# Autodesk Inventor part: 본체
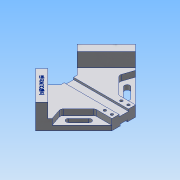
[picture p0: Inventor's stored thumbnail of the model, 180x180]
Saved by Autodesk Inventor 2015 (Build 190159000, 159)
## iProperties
Created: 2019-04
Part Number: 본체
Material: 알루미늄 6061
Document SubType Name: Modeling
Designer: user
Density: 2.7 g/cm^3
Appearance: 알루미늄 - 평지
Mass: 601.457 g
Surface Area: 426.592 cm^2
Volume: 222.762 cm^3
Author: user
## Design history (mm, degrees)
sketch "스케치1"
  geometry: L1 (84.853, 0)-(0, -84.853); L2 (0, -84.853)-(-84.853, 0); L3 (-84.853, 0)-(0, 84.853); L4 (0, 84.853)-(84.853, 0); L5 (-64.853, 20)-(-64.853, -20); L6 (49.497, 35.355)-(14.142, 0); L7 (14.142, 0)-(49.497, -35.355); L8 (28.147, 14.005)-(28.147, -14.005); 3 further points
  constraints: 16 end point, 6 point on line, 2 coincident, 2 vertical, 1 perpendicular, 9 other
  dimensions: "d3" = 120 distance of L1.start L1.end; "d4" = 84.85281 horizontal distance of L3.end L1.start; "d5" = 40 distance of L5.start L5.end; "d7" = 50 distance of L1.start L6.start; "d8" = 50 distance of L1.start L7.end; "d10" = 93 distance between parallel lines of L5 L8; "d11" = 50 distance of L6.start L6.end
extrude "돌출1" new body sketch "스케치1" distance "d12" = 18; taper "d13" = 0 deg
sketch "스케치2"
  geometry: L1 (-28.147, -14.005)-(-49.497, -35.355) reference; L2 (0, -84.853)-(64.853, -20) reference; L3 (10.607, -74.246)-(-38.891, -24.749); L4 (-28.147, -14.005)-(-49.497, -35.355) reference; L5 (-49.497, -35.355)-(0, -84.853) reference; L6 (0, -84.853)-(64.853, -20) reference; L7 (10.607, -74.246)-(0, -84.853); L8 (0, -84.853)-(-49.497, -35.355); L9 (-49.497, -35.355)-(-38.891, -24.749); 1 further point
  constraints: 8 end point, 4 point on line, 2 collinear, 2 perpendicular
  dimensions: "d14" = 15 distance of L2.start L3.start
extrude "돌출2" join sketch "스케치2" distance "d15" = 24; taper "d16" = 0 deg
sketch "스케치3"
  geometry: L1 (10.607, -74.246)-(64.853, -20) reference; L2 (64.853, -20)-(36.569, -20); L3 (36.569, -20)-(7.071, -49.497); L4 (7.071, -49.497)-(14.142, -70.711); L5 (-49.497, -35.355)-(0, -84.853) reference; L6 (64.853, -20)-(14.142, -70.711); 1 further point
  constraints: 8 end point, 1 collinear, 1 horizontal, 1 point on line
  dimensions: "d17" = 20 distance between parallel lines of L1 L3; "d18" = 20 distance from line of L5 L4.end; "d19" = 30 distance from line of L5 L3.end
extrude "돌출3" cut sketch "스케치3" distance "d20" = 10; taper "d21" = 0 deg
sketch "스케치4"
  geometry: L1 (7.071, -49.497)-(36.569, -20) reference; L2 (21.213, -49.497)-(38.184, -32.527); L3 (-49.497, -35.355)-(0, -84.853) reference; L4 (21.213, -49.497)-(38.184, -32.527); L5 (24.395, -52.679)-(41.366, -35.709); L6 (35.002, -29.345)-(18.031, -46.315); A1 r 4.5 centre (21.213, -49.497) between (18.031, -46.315) and (24.395, -52.679); A2 r 4.5 centre (38.184, -32.527) between (41.366, -35.709) and (35.002, -29.345); 2 further points
  constraints: 10 end point, 4 point on circle, 4 tangent, 2 centre point, 2 equal length, 1 midpoint
  dimensions: "d24" = 10 distance between parallel lines of L1 L2; "d25" = 24 distance of L2.start L2.end; "d26" = 40 distance from line of L3 L2.start; "d27" = 9 diameter of A2
extrude "돌출4" cut sketch "스케치4" distance "d28" = 8; taper "d29" = 0 deg
sketch "스케치5"
  geometry: L1 (0, 0)-(40, 0) reference; L2 (0, 18)-(40, 18) reference; L3 (12, 14.5)-(28, 14.5); L4 (28, 14.5)-(28, 18); L5 (28, 18)-(12, 18); L6 (12, 18)-(12, 14.5); L7 (14, 3)-(26, 3); L8 (26, 3)-(26, 0); L9 (26, 0)-(14, 0); L10 (14, 0)-(14, 3); 4 further points
  constraints: 16 end point, 5 midpoint, 4 parallel, 2 horizontal, 2 perpendicular, 1 coincident, 1 vertical alignment
  dimensions: "d30" = 3 distance of L7.end L8.end; "d31" = 3.5 distance of L3.end L4.end; "d32" = 16 distance of L3.start L3.end; "d33" = 12 distance of L7.start L7.end
extrude "돌출5" cut sketch "스케치5" stored distance "d34" = 0; taper "d35" = 0 deg
sketch "스케치6"
  geometry: L1 (-28.147, 6)-(64.853, 6) reference; L2 (64.853, 20)-(64.853, 6) reference; C1 r 4 at (58.853, 14); C2 r 4 at (46.853, 14); 1 further point
  constraints: 2 centre point, 1 horizontal alignment
  dimensions: "d36" = 8 distance from line of L1 C1.centre; "d37" = 12 distance of C2.centre C1.centre; "d38" = 6 distance from line of L2 C1.centre; "d39" = 8 diameter of C1; "d40" = 8 diameter of C2
extrude "돌출6" cut sketch "스케치6" distance "d41" = 10; taper "d42" = 0 deg
hole "구멍1" diameter "d45" = 4.5; stored, may be unused: countersink angle "d49" = 90 deg, drill point angle "d51" = 118 deg; dims "d43" = 10, "d44" = 10, "d46" = 6, "d47" = 4, "d48" = 2, "d50" = 8
hole "구멍2" diameter "d54" = 4.5; stored, may be unused: countersink angle "d58" = 90 deg, drill point angle "d60" = 118 deg; dims "d52" = 10, "d53" = 10, "d55" = 6, "d56" = 4, "d57" = 2, "d59" = 8
fillet "모깎기1" dims "d61" = 5
node "작업 평면1"
sketch "스케치7"
  geometry: L1 (38.891, 24.749)-(49.497, 35.355) reference; L2 (49.497, 35.355)-(0, 84.853) reference; 2 further points
  constraints: 1 other
  dimensions: "d63" = 35 distance from line of L1 point (19.445, 54.801); "d64" = 7.5 distance from line of L2 point (19.445, 54.801)
feature "엠보싱1" sketch "스케치7" dims "d3" = 120, "d4" = 84.85281, "d5" = 40, "d7" = 50, "d8" = 50, "d10" = 93, "d11" = 50, "d65" = 0.5, "d66" = 0
node "솔리드1"
mirror "대칭1"
other parameters: "d62" = 64.25
